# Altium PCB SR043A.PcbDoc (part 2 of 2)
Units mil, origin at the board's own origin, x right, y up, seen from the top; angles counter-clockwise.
Board outline 3937.01 x 3543.31 mil, 6 copper layers (Top Layer, Signal Layer 1, Signal Layer 2, Signal Layer 3, Signal Layer 4, Bottom Layer), stack 60.536 mil thick; 120 components, 36 nets, 230 pads, 513 vias.
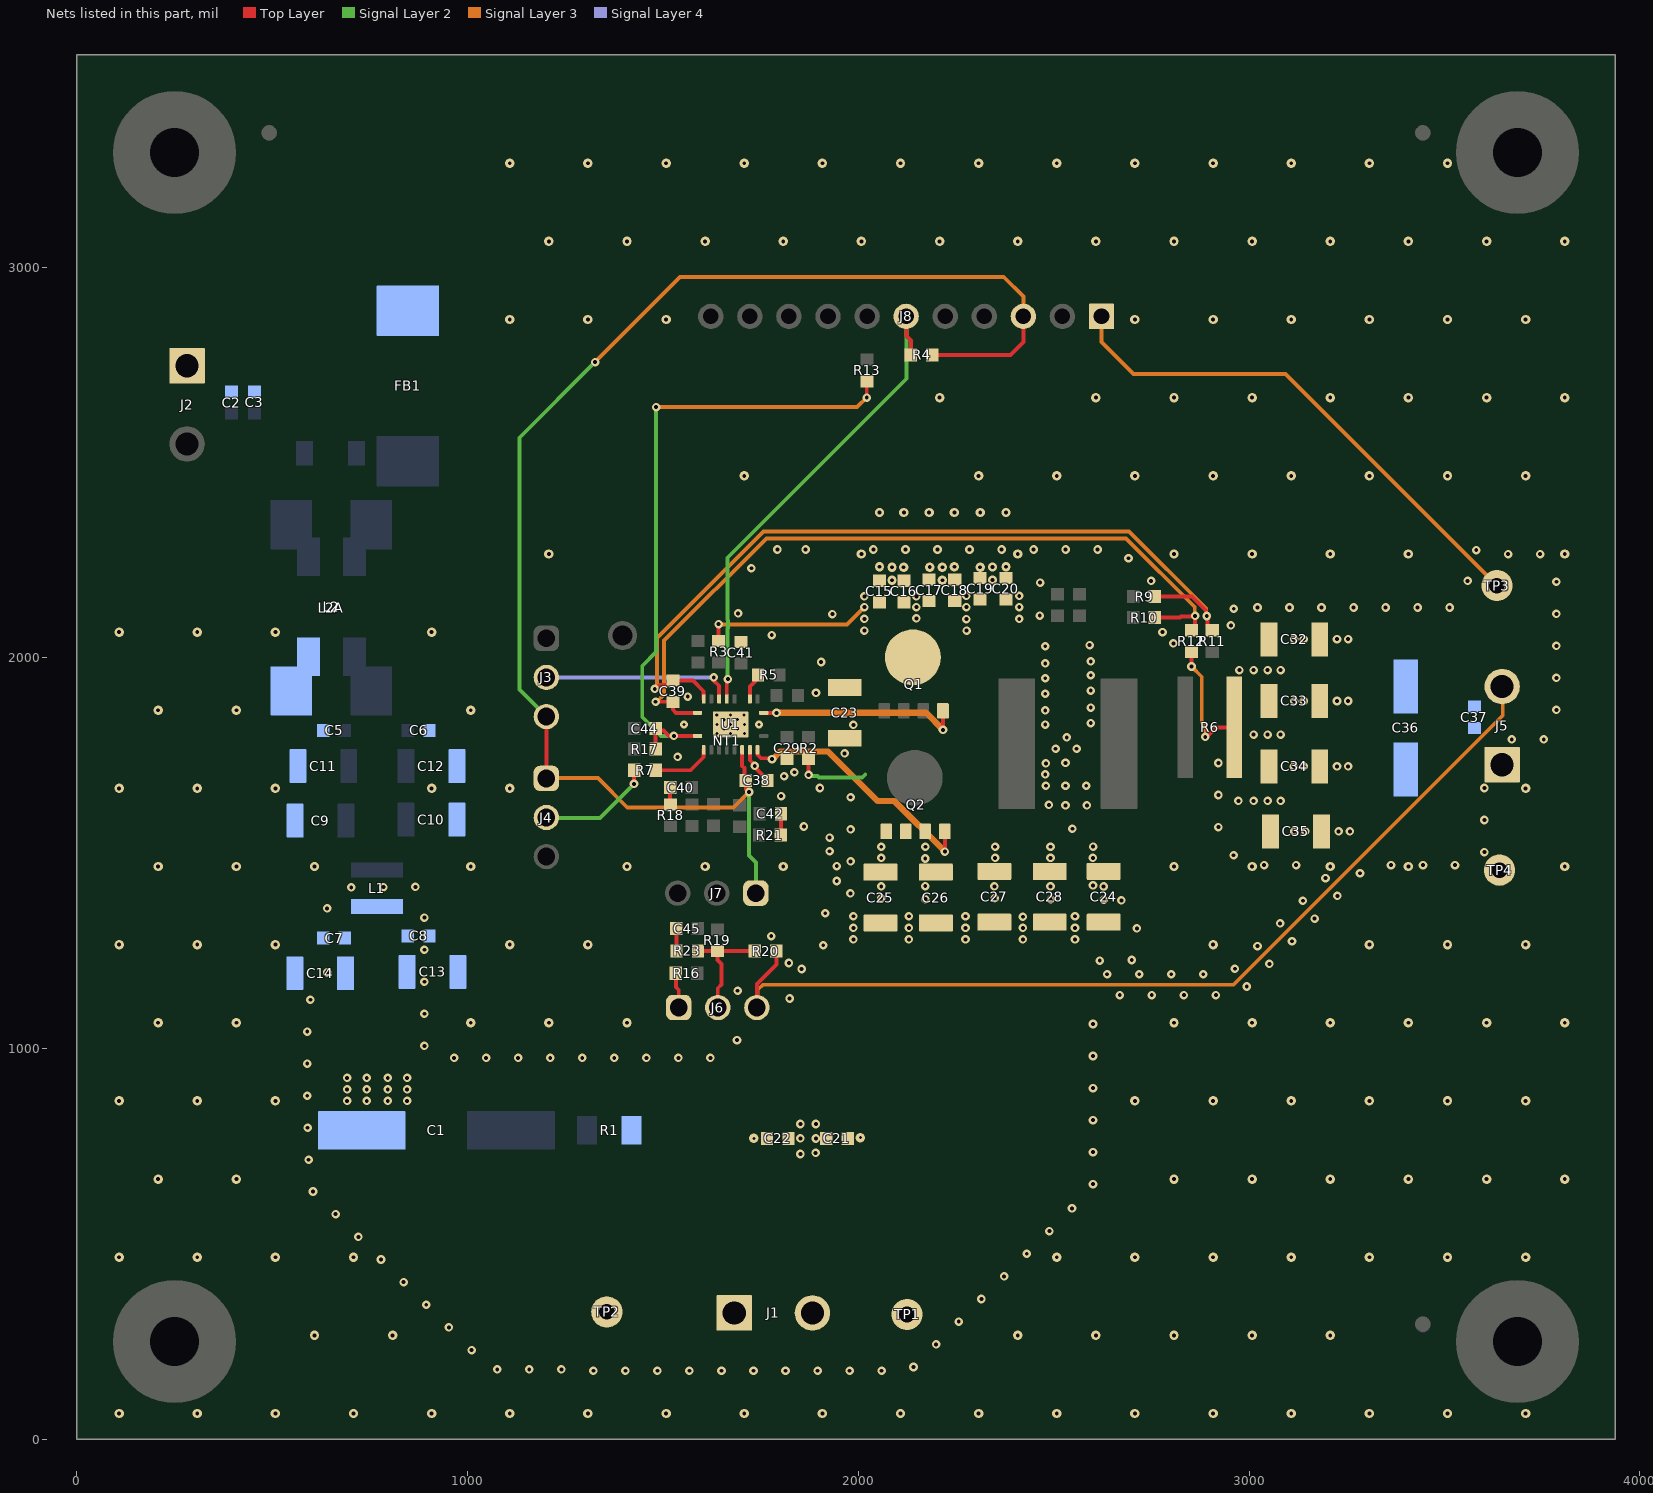
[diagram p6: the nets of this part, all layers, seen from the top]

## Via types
v1: diameter 22, hole 10, Top Layer to Bottom Layer, tented both sides, 318 vias
v2: diameter 24, hole 10, Top Layer to Bottom Layer, tented both sides, 178 vias
v3: diameter 19.68, hole 7.87, Top Layer to Bottom Layer, tented both sides, 15 vias
v4: diameter 24, hole 8, Top Layer to Bottom Layer, tented both sides, 2 vias

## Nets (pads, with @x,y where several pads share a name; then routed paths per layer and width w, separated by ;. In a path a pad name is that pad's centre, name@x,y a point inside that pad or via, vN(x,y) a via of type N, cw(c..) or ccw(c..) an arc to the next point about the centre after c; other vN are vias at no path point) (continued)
NetC39_1: C39.1 R10.1 R12.1 U1.19 | length 2005.3
  Top Layer w10: v1(1481.27,1887.68) 1524.54,1887.68 C39.1@1525.31,1886.91 1525.31,1867.22 1533.28,1859.25 U1.19@1588.58,1859.25 ; R10.1@2759.06,2103.12 2823,2103.12 2826.05,2106.16 2860.55,2106.16 v1(2861.88,2107.49) 2861.88,2079.63 R12.1@2852.78,2070.53
  Signal Layer 3 w10: v1(1481.27,1887.68) 1484.18,1887.68 1502.81,1906.31 1502.81,2043.95 1764.55,2305.69 2685.5,2305.69 2861.13,2130.07 2861.13,2108.25 v1(2861.88,2107.49)
NetC39_2: C39.2 R9.1 R11.2 U1.18 | length 2121.9
  Top Layer w10: v1(1478.94,1920.54) 1482.18,1920.54 1492.92,1931.28 1514.57,1931.28 C39.2@1525.31,1942.03 1525.54,1942.25 1576.61,1942.25 1604.25,1914.61 1604.25,1894.76 U1.18@1604.33,1894.69 ; R9.1@2759.06,2157.06 2854.02,2157.06 2889.46,2121.63 2889.46,2109.53 v1(2891.75,2107.23) 2894.05,2104.94 2894.05,2082.39 2894.18,2082.26 2894.18,2081.28 2904.93,2070.53 R11.2@2905.91,2070.53
  Signal Layer 3 w10: v1(1478.94,1920.54) 1478.94,1923.78 1484.44,1929.29 1484.44,2050.86 1757.15,2323.57 2692.9,2323.57 2889.46,2127.01 2889.46,2112.78 v1@2894,2108.24
NetC40_2: C40.2 R18.2 | length 43.6
  Top Layer w10: C40.2@1518.42,1667.92 1518.42,1626.15 R18.2@1519.73,1624.85
NetC42_2: C42.2 R21.1 | length 54.8
  Top Layer w10: R21.1@1801.15,1546.62 1802.02,1547.49 C42.2@1802.02,1601.08
NetC44_2: C44.2 R13.2 R17.2 U1.1 | length 1667.5
  Top Layer w10: R17.2@1481.4,1761.52 1481.4,1814.13 1501.2,1814.13 1515.13,1800.2 v1(1527.95,1800.2) U1.1@1588.58,1800.2 ; R17.2@1483.22,1769.18 R17.2@1484.2,1768.19 ; v1(2021.51,2666.01) 2021.51,2707.4 R13.2@2022.44,2708.33
  Signal Layer 2 w10: v1(1482.5,2641.59) 1482.5,2015.01 1447.03,1979.53 1447.03,1848.55 1495.38,1800.2 v1(1527.95,1800.2)
  Signal Layer 3 w10: v1(1482.5,2641.59) 1997.09,2641.59 v1(2021.51,2666.01)
NetC45_1: C45.1 R23.1 | length 57.6
  Top Layer w10: C45.1@1534.17,1307.09 1534.17,1250.46 R23.1@1534.84,1249.8
NetJ3_2: J3.2 U1.16 | length 489.4
  Top Layer w10: v1(1629.95,1949.89) 1629.86,1949.8 1629.86,1942.42 1643.7,1928.59 U1.16@1643.7,1894.69
  Signal Layer 4 w10: J3.2@1201.57,1949.89 v1(1629.95,1949.89)
NetJ4_2: J4.2 R7.2 | length 296
  Top Layer w10: v1(1425.97,1677.61) 1426.28,1677.92 1426.28,1682 R7.2@1426.28,1712.29
  Signal Layer 2 w10: J4.2@1201.57,1591.43 1202.88,1590.11 1338.47,1590.11 v1(1425.97,1677.61)
NetJ6_1: J6.1 R16.2 | length 90.8
  Top Layer w10: R16.2@1533.02,1192.73 1533.02,1157.11 1540.33,1149.81 J6.1@1540.33,1105.01
NetJ6_2: J6.2 R19.2 R20.1 R23.2 | length 298.1
  Top Layer w10: R23.2@1589.95,1249.8 1639.05,1249.8 R19.2@1639.31,1249.53 ; J6.2@1640.33,1105.01 1640.33,1154.32 1649.74,1163.72 1649.74,1216.73 1639.31,1227.16 R19.2@1639.31,1249.53 ; R20.1@1735.22,1249.53 R19.2@1639.31,1249.53
NetQ1_4: Q1.4 U1.11 | length 531.3
  Top Layer w10: U1.11@1757.87,1859.25 v1(1790.69,1859.25) ; v1(2216.73,1815.69) Q1.4@2216.73,1864.27
  Signal Layer 3 w10: v1@2210.83,1815.69 v1(2216.73,1815.69)
  Signal Layer 3 w16: v1(1790.69,1859.25) 2173.35,1859.25 v1@2216.73,1815.88
NetQ2_4: Q2.4 U1.9 | length 663.5
  Top Layer w10: U1.9@1742.13,1764.76 1742.13,1752.38 1751.32,1743.18 1776.89,1743.18 v1(1779.18,1740.89) ; v1(2221.48,1504.11) Q2.4@2221.48,1555.82
  Signal Layer 3 w10: v1(2221.48,1504.11) v1@2221.48,1505.82
  Signal Layer 3 w16: v1(1779.18,1740.89) 1780.81,1740.89 1800.43,1760.5 1922.18,1760.5 2049.28,1633.4 2092.66,1633.4 2220.24,1505.82 v1@2221.48,1505.82
NetR5_1: R5.1 U1.13 | length 62.2
  Top Layer w10: U1.13@1722.44,1894.69 1722.44,1926.6 1743.19,1947.35 R5.1@1743.19,1948.33
NetR7_1: R7.1 U1.2 | length 155.9
  Top Layer w10: R7.1@1481.4,1712.29 1570.95,1712.29 1604.25,1745.59 1604.25,1764.69 U1.2@1604.33,1764.76
PG: J8.6 R4.1 U1.15 | length 1275.7
  Top Layer w10: U1.15@1663.39,1894.69 1663.39,1942.59 v1(1666.31,1945.51) ; J8.6@2123.05,2874.02 2123.05,2824.02 2135.08,2811.99 R4.1@2135.08,2775.59
  Signal Layer 2 w10: v1(1666.31,1945.51) 1664.93,1946.89 1664.93,2075.13 1666.3,2076.5 1666.3,2096.27 1664.93,2097.64 1664.93,2256.31 2123.05,2714.43 2123.05,2873.41 J8.6@2122.44,2874.02
PGND: C5.2 C6.2 C7.2 C8.2 C9.1 C10.1 C11.1 C12.1 C13.1 C14.1 C15.2 C16.2 C17.2 C18.2 C19.2 C20.2 C21.2 C22.2 C23.1 C24.1 C25.1 C26.1 C27.1 C28.1 C29.1 C32.2 C33.2 C34.2 C35.2 C36.2 C37.2 C38.2 C41.2 J1.1 J5.1 L2.2 L2A.3 NT1.1 Q2.1 Q2.2 Q2.3 R1.2 TP2.1 TP4.1 U1.8 U1.20 | length 96.7
  Top Layer w10: U1.8@1722.44,1764.76 1722.44,1737.95 1735,1725.39 v1(1735,1723.62) 1737.3,1721.33 1737.3,1717.65 1767.34,1687.6 C38.2@1767.34,1686.62
  other v1: 1321.74,175.44 1403.74,175.44 1485.74,175.44 1567.74,175.44 1649.74,175.44 1731.74,175.44 1813.74,175.44 1895.74,175.44 1977.74,175.44 2059.74,175.44 1075.82,179.08 1157.82,179.08 1239.82,179.08 2141.18,185 1010.25,228.32 2199.16,242.98 952.27,286.3 2257.15,300.96 894.28,344.28 2315.13,358.94 836.3,402.26 2373.11,416.93 778.32,460.25 2431.1,474.91 720.33,518.23 2489.08,532.89 662.35,576.21 2547.06,590.88 604.37,634.19 2600.6,652.99 593.08,715.41 2600.67,734.99 590.49,797.37 2600.67,816.99 589.6,879.37 2600.67,898.99 589.6,961.37 965.46,976.14 1047.46,976.14 1129.46,976.14 1211.46,976.14 1293.46,976.14 1375.46,976.14 1457.46,976.14 1539.46,976.14 1621.46,976.14 2600.67,980.99 889.52,1007.07 1689.64,1021.69 589.6,1043.37 2600.67,1062.99 889.52,1089.07 597.5,1124.99 1824.18,1128.1 2669.16,1136.62 2751.16,1136.62 2833.16,1136.62 2915.16,1136.62 1691.12,1148.13 2994.09,1158.86 889.52,1171.07 2636.97,1190.27 2718.97,1190.27 2800.97,1190.27 2882.97,1190.27 640.45,1194.84 1855.03,1203.8 2963.74,1204.38 3052.07,1216.84 1822.22,1219.15 2617.9,1225.16 2699.88,1226.83 889.52,1253.07 3021.73,1262.37 1910.16,1264.5 3110.05,1274.83 1777.18,1287.67 2713.03,1307.77 3079.71,1320.35 3168.04,1332.81 889.52,1335.07 1915.36,1346.34 640.45,1358.84 3137.69,1378.33 2673.17,1379.43 2627.95,1381.43 2492.04,1381.72 2171.48,1382.57 2058.69,1384.59 2348.99,1384.55 3226.02,1390.79 1979.7,1397.18 702.25,1412.73 784.25,1413.39 866.25,1413.7 2058.69,1415.11 2348.15,1415.11 2491.85,1415.11 2627.77,1414.81 2171.24,1415.63 2600.67,1417.75 1944.79,1428.83 3195.68,1436.31 3284,1448.77 1944.79,1466.88 3038.73,1469.59 3120.73,1469.59 3363.32,1469.59 3445.32,1469.59 3527.32,1469.59 1980.19,1479.18 2171.24,1486.62 2058.69,1488.03 2350.12,1488.03 2491.85,1488.03 2600.39,1488.03 2960.74,1494.91 3602.23,1502.94 1926.57,1505.06 2058.69,1516.57 2171.48,1516.57 2350.12,1516.57 2491.85,1516.57 2600.88,1517.01 1926.57,1539.75 3115.7,1555.49 3144.14,1555.82 3229.52,1555.82 3258.07,1555.82 1980.19,1561.18 2548.06,1562.65 2921.5,1566.92 1860.81,1568.28 3602.23,1584.94 2530.32,1622.58 2584.94,1622.58 2487.86,1623.71 1980.19,1643.18 1802.42,1646.31 2921.5,1648.92 1901.7,1666.91 3602.23,1666.94 2479.95,1672.61 2530.32,1672.61 2583.35,1672.61 1810.02,1697.11 2478.51,1701.81 1836.49,1707.29 3114.99,1721.5 3139.76,1722.34 3225.15,1722.34 3253.69,1722.34 2479.95,1730.06 2530.32,1731.05 2921.5,1730.92 1537.72,1746.53 1965.17,1755.52 2504.95,1767.37 2558.75,1767.37 3672.42,1791.34 3754.42,1791.34 2533.57,1796.63 1987.2,1828.38 2478.51,1829.25 2594.9,1832.87 2478.51,1865.81 3786.55,1866.78 2594.9,1872.58 3115.35,1889.27 3139.76,1889.66 3225.15,1889.66 3253.69,1889.66 1563.46,1900.64 2478.51,1908.28 1891.64,1910.3 2594.9,1916.01 2478.51,1947.81 3786.55,1948.78 2594.9,1955.63 2478.51,1986.1 1904.98,1989.41 2594.9,1991.14 2478.51,2029.81 3786.55,2030.78 2591.91,2032.7 2806.22,2037.29 3115.35,2047.15 3139.76,2048.13 3225.15,2048.13 3253.69,2048.13 1778.49,2058.29 2778.59,2065.73 2953.53,2083.3 2464.31,2108.25 1933.66,2111.94 3786.55,2112.78 1692.54,2113.79 2960.95,2125.71 3021.61,2129.01 3103.61,2129.01 3185.61,2129.01 3267.61,2129.01 3349.61,2129.01 3431.61,2129.01 3513.61,2129.01 2465.3,2192.74 3786.55,2194.78 2749.6,2197.1 3559.4,2197.04 1726.2,2229.41 2691.62,2255.08 3663.06,2265.51 3745.06,2265.51 3581.71,2275.8 1792.71,2277.38 1865.36,2277.38 2038.71,2277.38 2120.71,2277.38 2202.71,2277.38 2284.71,2277.38 2366.71,2277.38 2448.71,2277.38 2530.71,2277.38 2612.71,2277.38
  other v2: 108,66 308,66 508,66 708,66 908,66 1108,66 1308,66 1508,66 1708,66 1908,66 2108,66 2308,66 2508,66 2708,66 2908,66 3108,66 3308,66 3508,66 3708,66 608,266 808,266 2408,266 2608,266 2808,266 3008,266 3208,266 108,466 308,466 508,466 708,466 2508,466 2708,466 2908,466 3108,466 3308,466 3508,466 3708,466 208,666 408,666 2808,666 3008,666 3208,666 3408,666 3608,666 3808,666 108,866 308,866 508,866 2708,866 2908,866 3108,866 3308,866 3508,866 3708,866 208,1066 408,1066 1008,1066 1208,1066 1408,1066 2808,1066 3008,1066 3208,1066 3408,1066 3608,1066 3808,1066 108,1266 308,1266 508,1266 1108,1266 1308,1266 2908,1266 3308,1266 3508,1266 3708,1266 208,1466 408,1466 608,1466 1008,1466 1408,1466 1608,1466 1808,1466 2808,1466 3008,1466 3208,1466 3408,1466 3808,1466 108,1666 308,1666 508,1666 908,1666 1108,1666 3708,1666 208,1866 408,1866 1008,1866 108,2066 308,2066 508,2066 908,2066 2086.25,2198.7 2215.33,2198.7 2343.38,2199.38 2086.25,2231.95 2116.04,2231.95 2182.86,2232.25 2215.33,2231.95 2311.77,2231.98 2054.23,2233.3 2245.99,2233.3 2343.38,2232.62 2377.95,2233.3 1208,2266 2008,2266 2408,2266 2808,2266 3008,2266 3208,2266 3408,2266 3808,2266 2054.23,2372.05 2116.73,2372.05 2181.1,2372.05 2245.99,2372.05 2312.01,2372.05 2377.95,2372.05 1708,2466 2308,2466 2508,2466 2708,2466 2908,2466 3108,2466 3308,2466 3508,2466 3708,2466 2208,2666 2608,2666 2808,2666 3008,2666 3208,2666 3408,2666 3608,2666 3808,2666 1108,2866 1308,2866 1508,2866 2708,2866 2908,2866 3108,2866 3308,2866 3508,2866 3708,2866 1208,3066 1408,3066 1608,3066 1808,3066 2008,3066 2208,3066 2408,3066 2608,3066 2808,3066 3008,3066 3208,3066 3408,3066 3608,3066 3808,3066 1108,3266 1308,3266 1508,3266 1708,3266 1908,3266 2108,3266 2308,3266 2508,3266 2708,3266 2908,3266 3108,3266 3308,3266 3508,3266
  other v3: 1673.23,1806.1 1638.04,1806.65 1708.2,1806.65 1655.76,1818 1690.69,1818 1553.86,1829.38 1745.67,1829.38 1637.8,1829.73 1673.23,1829.73 1708.66,1829.73 1655.76,1841.65 1690.69,1841.85 1637.73,1853.35 1673.23,1853.35 1707.92,1853.35
  other v4: 1732.58,770.18 2005.25,772.15
VCC: C38.1 J3.3 J4.1 J7.1 J8.3 R4.2 U1.7 | length 3699.5
  Top Layer w10: J4.1@1201.57,1691.43 J3.3@1201.57,1849.89 ; U1.7@1702.76,1764.76 1702.76,1723.39 1708.38,1717.77 1708.38,1690.46 C38.1@1712.23,1686.62 1712.23,1662.47 1718.08,1656.61 v1(1720.6,1656.61) ; R4.2@2188.86,2775.59 2390.05,2775.59 2422.44,2807.98 J8.3@2422.44,2874.02
  Signal Layer 2 w10: J3.3@1201.57,1849.89 1132.83,1918.62 1132.83,2563.47 v1(1326.25,2756.89) ; v1(1720.6,1656.61) 1720.6,1493.93 1738.4,1476.13 1738.4,1398.56 J7.1@1737.67,1397.83
  Signal Layer 3 w10: J4.1@1201.57,1680.71 1202.54,1680.71 1214.19,1692.36 1333.32,1692.36 1408.61,1617.07 1681.05,1617.07 v1(1720.6,1656.61) ; v1(1326.25,2756.89) 1543.96,2974.6 2372.27,2974.6 2422.44,2924.42 J8.3@2422.44,2874.02
VIN: C1.2 C7.1 C8.1 C13.2 C14.2 C15.1 C16.1 C17.1 C18.1 C19.1 C20.1 C21.1 C22.1 C23.2 C24.2 C25.2 C26.2 C27.2 C28.2 J1.2 L1.2 Q1.5-6 R2.2 R3.2 TP1.1 | length 627.4
  Top Layer w10: R3.2@1642.42,2043.35 R3.2@1642.51,2043.43 1642.42,2043.51 v1(1642.42,2086.39) ; v1(1872.94,1700.44) R2.2@1872.94,1741.62
  Signal Layer 2 w10: v1(1872.94,1700.44) 1875.23,1698.14 1895.11,1698.14 1899.52,1693.74 2010.06,1693.74 2017.87,1701.55
  Signal Layer 3 w10: v1(1642.42,2086.39) 1643.69,2085.12 1970.66,2085.12 v1(2015.48,2129.94)
  other v1: 1851.6,730.28 1890.74,733.19 1851.6,770.11 1891.35,769.95 1851.6,807.09 1891.35,807.09 691.72,866.14 741.97,866.14 795.72,866.14 845.21,866.14 691.72,895.67 741.97,895.67 795.72,895.67 845.22,895.67 691.72,925.2 741.97,925.2 795.72,925.2 845.22,925.2 1987.2,1279.53 2129.53,1279.53 2274.33,1279.53 2421.26,1279.53 2554.57,1279.53 1987.2,1309.06 2129.53,1309.06 2274.33,1309.06 2421.26,1309.06 2554.57,1309.06 2421.26,1337.45 1987.2,1338.58 2129.53,1338.58 2274.33,1338.58 2554.57,1338.58 2015.48,2069.63 2277.05,2069.79 2276.79,2099 2015.48,2099.89 2411.85,2099.89 2148.52,2101 2148.45,2129.94 2276.79,2129.94 2411.85,2129.94 2015.48,2157.33 2148.45,2157.33 2276.79,2158.79 2411.85,2158.79
VIN_EMI: C2.1 C3.1 FB1.1 J2.1
VOUT: C32.1 C33.1 C34.1 C35.1 C36.1 C37.1 J5.2 J6.3 J8.1 R6.2 R12.2 R20.2 TP3.1 | length 4156.4
  Top Layer w10: J6.3@1740.33,1105.01 1740.33,1165.01 1790.34,1215.01 R20.2@1790.34,1249.53 ; v1(2852.78,1978.03) R12.2@2852.78,2015.41 ; v1(2888.04,1797.89) 2891.21,1797.89 2915.27,1821.95 R6.2@2962.6,1821.95
  Signal Layer 2 w10: TP3.1@3634.54,2185.04 TP3.1@3647.27,2172.31 ; J5.2@3640.11,1902.9 J5.2@3640.79,1903.57 ; J5.2@3647.27,1927.24 J5.2@3647.99,1926.52
  Signal Layer 3 w10: J6.3@1740.33,1105.01 1742.7,1107.38 1742.7,1150.52 1755.63,1163.44 2960.74,1163.44 3649.38,1852.09 3649.38,1925.12 J5.2@3647.99,1926.52 ; J8.1@2622.44,2874.02 2622.44,2808.73 2704.79,2726.38 3093.2,2726.38 TP3.1@3634.54,2185.04 ; v1(2852.78,1978.03) 2879.05,1951.76 2879.05,1834.7 2888.04,1825.72 v1(2888.04,1797.89)
  other v1: 2972.84,1633.86 3011.96,1633.86 3047.46,1633.86 3080.71,1633.86 3011.96,1803.44 3047.46,1803.44 3080.71,1803.44 2975.51,1968.5 3011.96,1968.5 3047.46,1968.5 3080.71,1968.5
pads on no net: FID1.1 FID2.1 FID3.1 FID4.1 FID5.1 FID6.1 H1.1 H2.1 H3.1 H4.1 H5.0 H6.0 H7.0 H8.0

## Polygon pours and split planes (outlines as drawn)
NetC30_1 on Top Layer "TOP_LAYER_NETC30_1_P159" (solid, remove dead copper, pour order 159): 2038.6,1626.29 2038.6,1874.31 cw(c2049.24,1874.34) 2049.32,1884.98 2184.19,1883.93 cw(c2184.14,1876.63) 2191.43,1876.63 2191.43,1814.3 ccw(c2208.25,1814.3) 2208.25,1797.48 2331.67,1797.48 2354.29,1820.1 2354.29,1944.75 cw(c2358.38,1944.75) 2358.38,1948.84 2449.12,1948.84 cw(c2449.12,1942.15) 2455.8,1942.15 2455.8,1622.11 cw(c2442.96,1622.11) 2442.92,1609.27 2054.44,1610.4 cw(c2054.49,1626.29)
PGND on Top Layer "TOP_LAYER_PGND_P175" (solid, remove dead copper, pour order 175): 1572.33,1714.37 1501.08,1714.37 1501.08,1778.86 1572.33,1778.86
VIN on Top Layer "TOP_LAYER_VIN_P156" (solid, remove dead copper, pour order 156): 1985.24,1921.69 1919.19,1921.69 1919.19,1928.15 1919.19,1969.48 cw(c1929.25,1969.48) 1929.25,1979.53 1953.42,1979.53 ccw(c1953.42,1996.77) 1970.66,1996.77 1970.66,2170.16 2434.76,2170.16 2434.76,2077.78 2287.51,2077.78 2287.51,1921.69
VIN on Top Layer "TOP_LAYER_VIN_P154" (solid, remove dead copper, pour order 154): 2691.62,1358.02 2691.62,1246.57 1936.77,1246.57 1936.77,1358.02
PGND on Top Layer "TOP_LAYER_PGND_P160" (solid, remove dead copper, pour order 160): 2614.49,1393.11 1935.94,1393.11 1935.94,1580.22 2614.74,1580.22
PGND on Top Layer "TOP_LAYER_PGND_P155" (solid, remove dead copper, pour order 155): 2434.69,2244.14 1972.15,2244.14 1970.51,2245.78 1970.51,2431.25 2434.94,2431.25
NetC31_2 on Top Layer "TOP_LAYER_NETC31_2_P158" (solid, remove dead copper, pour order 158): 2614.49,1609.07 2856.69,1609.07 2856.69,2008.06 2848.88,2015.87 2614.74,2015.87
VOUT on Top Layer "TOP_LAYER_VOUT_P157" (solid, remove dead copper, pour order 157): 3093.45,1491 3093.45,2102.26 3002.77,2102.26 2942.91,2042.4 2942.91,1543.02 2994.94,1491
PGND on Top Layer "TOP_LAYER_PGND_P161" (solid, remove dead copper, pour order 161): -0.58,0.56 -0.58,3543.87 3936.42,3543.87 3936.42,0.56
AGND on Top Layer "TOP_LAYER_AGND_P153" (solid, remove dead copper, pour order 153): 1779.96,1589.07 1779.96,1532.25 1771.38,1523.67 1394.04,1523.67 1361.41,1556.3 1361.41,1859.48 1377.57,1875.64 1447.03,1875.64 1447.03,1835.62 1488.29,1835.62 1488.29,1607.1 1500.07,1595.32 1773.71,1595.32
VIN on Top Layer "TOP_LAYER_VIN_P152" (solid, remove dead copper, pour order 152): 1940.03,712.31 1939.56,712.78 1799.86,712.78 1799.86,827.59 1940.03,827.59
VIN on Signal Layer 2 "SIGNAL_LAYER_2_VIN_P164" (solid, remove dead copper, pour order 164): 2579.26,1501.16 2579.26,653.36 2122.76,196.85 1283.17,196.85 1279.53,200.49 1068.35,200.49 616.63,652.22 616.63,954.72 1581.94,954.72 1657.75,954.72 1936.56,1261.72 1936.56,1323.76 1972.38,1359.58 2001.6,1388.8 2001.6,2172.96 2457.1,2172.96 2457.1,1623.32
VOUT on Signal Layer 2 "SIGNAL_LAYER_2_VOUT_P163" (solid, remove dead copper, pour order 163): 3008.11,2107.6 3580.81,2107.6 3580.81,2244.09 3765.14,2244.09 3765.14,2107.6 3765.14,1812.75 3580.81,1812.75 3580.81,1491 2994.94,1491 2942.91,1543.02 2942.91,2042.4
PGND on Signal Layer 2 "SIGNAL_LAYER_2_PGND_P165" (solid, remove dead copper, pour order 165): 0,0 0,3543.31 3937.01,3543.31 3937.01,0
NetC5_1 on Bottom Layer "BOTTOM_LAYER_NETC5_1_P169" (solid, remove dead copper, pour order 169): 666.78,2073.08 666.78,1431.68 869.09,1431.68 869.09,2074.62 852.9,2090.76 683.95,2090.3
PGND on Bottom Layer "BOTTOM_LAYER_PGND_P174" (solid, remove dead copper, pour order 174): -0.49,-5.7 6.78,2090.81 1013.29,2090.81 1013.29,3537.6 3936.52,3537.6 3936.52,-5.7
NetC4_1 on Bottom Layer "BOTTOM_LAYER_NETC4_1_P170" (solid, remove dead copper, pour order 170): 675.88,2578.63 675.88,2165.44 695.66,2145.67 935.04,2145.67 953.03,2163.66 953.03,2580.92 927.72,2606.23 703.48,2606.23
"EMI GND" on Bottom Layer "BOTTOM_LAYER_EMI_GND_P173" (solid, remove dead copper, pour order 173): 25.49,3543.31 616.14,3543.31 935.04,3543.31 935.04,3281.98 935.04,3113.11 625.44,3113.11 625.44,2160.92 600.35,2135.83 25.49,2135.83
VIN_EMI on Bottom Layer "BOTTOM_LAYER_VIN_EMI_P172" (solid, remove dead copper, pour order 172): 196.12,3090.55 886.34,3090.55 942.97,3033.93 942.97,2742.04 871.88,2670.96 173.9,2670.96 127.08,2717.77 127.08,3021.51
VOUT on Bottom Layer "BOTTOM_LAYER_VOUT_P168" (solid, remove dead copper, pour order 168): 3703.36,1855.61 3366.14,1855.61 3366.14,1998.44 3702.89,1998.44
VIN on Bottom Layer "BOTTOM_LAYER_VIN_P171" (solid, remove dead copper, pour order 171): 661.86,1391 661.86,1108.76 611.01,1108.76 611.01,726.38 868.11,726.38 868.11,1392.66
PGND on Signal Layer 1 "SIGNAL_LAYER_1_PGND_P162" (solid, remove dead copper, pour order 162): 984.25,0 0,0 0,1965.83 0,3543.31 3937.01,3543.31 3937.01,0
PGND on Signal Layer 3 "SIGNAL_LAYER_3_PGND_P166" (solid, remove dead copper, pour order 166): 0,0 0,3543.31 3937.01,3543.31 3937.01,0
PGND on Signal Layer 4 "SIGNAL_LAYER_4_PGND_P167" (solid, remove dead copper, pour order 167): 0,0 0,3543.31 3937.01,3543.31 3937.01,0

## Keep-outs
Keep-Out Layer:
  lines w10: 6.82,0 3937.01,0 3937.01,3543.31 6.82,3543.31 6.82,0
  text ".Layer_Name" at 577,-858.49 h60

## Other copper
Top Layer:
  pour cut-out: 1712,1876.21 1697.24,1876.21 1697.24,1902.78 1711.8,1917.34
  pour cut-out: 1899.67,1816.42 1899.67,1843.96 1854.24,1843.96 1854.24,1816.42
  text ".Layer_Name" at 577,-858.49 h60
Signal Layer 1:
  text ".Layer_Name" at 570.87,-856.3 h60
Signal Layer 2:
  text ".Layer_Name" at 570.87,-856.3 h60
Signal Layer 3:
  text ".Layer_Name" at 570.87,-856.3 h60
Signal Layer 4:
  text ".Layer_Name" at 570.87,-856.3 h60
Bottom Layer:
  text ".Layer_Name" at 577,-858.49 h60

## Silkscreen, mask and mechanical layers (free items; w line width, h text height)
Top Overlay:
  drawing of 153 lines, arcs and shapes, not listed
  text "LM5190QEVM-400" at 640.37,3145.1 h108.27
  text "'.PRJ_Number'.PCB_Rev" at 651.64,3021.65 h108.27
  text "FB" at 2342.52,2974.6 h30 r90
  text "EN" at 1642.52,2968.6 h30 r90
  text "AGND" at 1744,2968.6 h30 r90
  text "ILIM/IMON" at 1842.52,2968.6 h30 r90
  text "AGND" at 1950.43,2968.6 h30 r90
  text "ISET" at 2043.64,2968.6 h30 r90
  text "PG" at 2148.41,2968.6 h30 r90
  text "COMP" at 2239.76,2968.6 h30 r90
  text "VCC" at 2442.52,2968.6 h30 r90
  text "BIAS" at 2535.24,2968.6 h30 r90
  text "VOUT" at 2636.44,2968.6 h30 r90
  text "VIN_EMI+" at 94.58,2916.21 h40
  text "4A MAX" at 594.35,2546.36 h40 r90
  text "VIN_EMI-" at 95.34,2310.66 h40
  text "MODE: J3" at 410.97,2065.48 h30
  text "VOUT+" at 3561.22,2060.23 h40
  text "AGND" at 1019.29,2040.72 h30
  text "1-2: PFM" at 415.07,1978.97 h30
  text "FPWM/SYNC" at 874.11,1939.12 h30
  text "2-3: FPWM" at 409.07,1916.7 h30
  text "OPEN: EXT SYNC" at 409.07,1859.62 h30
  text "VCC" at 1047.42,1831.94 h30
  text "RT: J4" at 399.16,1708.98 h30
  text "8A MAX" at 3379.83,1706.5 h40 r90
  text "VCC" at 1039,1677.71 h30
  text "1-2: DRSS ON" at 403.25,1622.47 h30
  text "RT" at 1059.15,1576.17 h30
  text "2-3: DRSS OFF" at 397.25,1560.2 h30
  text "VOUT-" at 3559.26,1544.01 h40
  text "AGND" at 1019.29,1468.44 h30
  text "FB: J7" at 907.82,1370.98 h30
  text "VCC" at 1793.67,1370.36 h30
  text "AGND" at 1349.11,1366.07 h30
  text "FB" at 1734,1298.42 h30
  text "1-2: 12VOUT" at 907.82,1287.98 h30
  text "2-3: 5VOUT" at 904.62,1228.41 h30
  text "OPEN: ADJ VOUT" at 910.62,1160.64 h30
  text "TRIM" at 1551.78,900.72 h30 r90
  text "BODE-" at 1659.21,900.72 h30 r90
  text "BODE+" at 1759.04,900.72 h30 r90
  text "7A MAX" at 1665.98,586.71 h40
  text "VIN-" at 1312.8,173.26 h40
  text "VIN+" at 2061.59,173.32 h40
  text ".Layer_Name" at 577,-858.49 h60
Bottom Overlay:
  text ".Layer_Name" at 577,-858.49 h60
Top Paste:
  text ".Layer_Name" at 577,-858.49 h60
Bottom Paste:
  text ".Layer_Name" at 577,-858.49 h60
Top Solder:
  text ".Layer_Name" at 577,-858.49 h60
  text ".Layer_Name" at 577,-858.49 h60
Bottom Solder:
  text ".Layer_Name" at 577,-858.49 h60
Drill Guide:
  text ".Layer_Name" at 577,-858.49 h60
M1 Board Outline:
  lines w10: 6.65,0 3937.01,0 3937.01,3543.31 6.65,3543.31 6.65,0
  text ".Layer_Name" at 577,-858.49 h60
M2 Board Dimensions:
  rectangle: 0,-275 125,-150
  rectangle: 125,-400 500,-275
  lines w7: 0,-275 1000,-275 ; 125,-400 125,-150 ; 250,-400 250,-150 ; 500,-400 500,-150 ; 750,-400 750,-150 ; 0,-400 1000,-400 1000,-150 0,-150 0,-400
  text ".Layer_Name" at 577,-858.49 h60
M3 3D STEP Top:
  text ".Layer_Name" at 577,-858.49 h60
M4 3D STEP Bottom:
  text ".Layer_Name" at 577,-858.49 h60
M5 Assembly Top:
  lines w10: -292,-930.17 6308,-930.17 ; -292,-726.83 6310,-726.83 ; -292,-523.5 -292,-1133.5 3713,-1133.5 6310,-1133.5 6310,-523.5 -291.5,-523.5 -291.5,-1133.5 1284,-1133.5 ; 2173,-1133.5 2173,-523.5 ; 3440,-726.83 3440,-523.5 ; 4280,-726.83 4280,-523.5 ; 4902,-1140 4902,-937.17
  text "COMPONENTS MARKED 'DNP' SHOULD NOT BE POPULATED." at 1153.5,-318.5 h60
  text "ASSEMBLY VARIANT:" at 1153,-434 h60
  text ".VariantName" at 2189,-434 h60
  text "PCB VIEWED FROM TOP SIDE" at -228.5,-655.67 h60
  text "BOARD #:" at 2248,-655.67 h60
  text ".PRJ_Number" at 2793.5,-655.67 h60
  text "REV:" at 3638,-655.67 h60
  text ".PCB_Rev" at 3929.5,-655.67 h60
  text "SVN REV:" at 4476,-655.67 h60
  text ".VersionControl_RevNumber" at 4982,-655.67 h60
  text "TID #:" at 2248,-859 h60
  text ".TID" at 2793.5,-859 h60
  text "PLOT NAME =" at -228.5,-1064.34 h60
  text ".plot_File_Name" at 577,-1064.34 h60
  text "GENERATED    :" at 2250,-1064.34 h60
  text ".Print_Date" at 3119.5,-1064.34 h60
  text ".Print_Time" at 3848.5,-1064.34 h60
  text "TEXAS INSTRUMENTS" at 5113,-1064.34 h60
M6 Assembly Bottom:
  lines w10: -292.5,-727.33 6309.5,-727.33 ; -290.5,-930.67 6309.5,-930.67 ; 1115.5,-1140.5 1115.5,-937.67 ; 1737.5,-727.33 1737.5,-524 ; 2577.5,-727.33 2577.5,-524 ; 3844.5,-1134 3844.5,-524 ; 4733.5,-1134 6309,-1134 6309,-524 -292.5,-524 -292.5,-1134 2304.5,-1134 6309.5,-1134 6309.5,-524
  text "COMPONENTS MARKED 'DNP' SHOULD NOT BE POPULATED." at 6102,-318 h60
  text ".VariantName" at 5058,-434 h60
  text "ASSEMBLY VARIANT:" at 6097,-434 h60
  text ".VersionControl_RevNumber" at 1035.5,-656.17 h60
  text "SVN REV:" at 1541.5,-656.17 h60
  text ".PCB_Rev" at 2088,-656.17 h60
  text "REV:" at 2379.5,-656.17 h60
  text ".PRJ_Number" at 3224,-656.17 h60
  text "BOARD #:" at 3769.5,-656.17 h60
  text "PCB VIEWED FROM BOTTOM SIDE" at 6246,-656.17 h60
  text ".TID" at 3224,-859.5 h60
  text "TID #:" at 3769.5,-859.5 h60
  text "TEXAS INSTRUMENTS" at 904.5,-1064.84 h60
  text ".Print_Time" at 2169,-1064.84 h60
  text ".Print_Date" at 2898,-1064.84 h60
  text "GENERATED    :" at 3767.5,-1064.84 h60
  text ".plot_File_Name" at 5440.5,-1064.84 h60
  text "PLOT NAME =" at 6246,-1064.84 h60
M9 Title Sheet:
  drawing of 57 lines, arcs and shapes, not listed
  text "1" at 739.84,8036.5 h70
  text "2" at 3235.5,8036.5 h70
  text "3" at 5724.84,8036.5 h70
  text "4" at 8231.51,8036.5 h70
  text "5" at 10730.5,8036.5 h70
  text "6" at 13235.5,8036.5 h70
  text "A" at -416.5,6893.5 h70
  text "A" at 14383.5,6893.5 h70
  text "B" at -416.5,4513.5 h70
  text "B" at 14383.5,4513.5 h70
  text "C" at -416.5,2138.5 h70
  text "C" at 14383.5,2138.5 h70
  text "PROJECT TITLE:" at 11343.5,277.5 h45
  text ".PRJ_Title" at 11393.5,144.17 h70
  text "DESIGNED FOR:" at 11343.5,-23.5 h45
  text ".PRJ_Customer" at 11393.5,-163.5 h70
  text "D" at -416.5,-231.5 h70
  text "D" at 14383.5,-231.5 h70
  text "FILE NAME:" at 11343.5,-323.5 h45
  text ".PCB_File_Name_No_Path" at 11393.5,-443.5 h70
  text "Texas Instruments (TI) and/or its licensors do not warrant the accuracy or completeness of this specification" at 6374,-605.34 h45
  text "ENGINEER:" at 11343.5,-613.5 h45
  text "LAYOUT BY:" at 12848.5,-613.5 h45
  text "or any information contained therein. TI and/or its licensors do not warrant that this design will meet" at 6329.01,-718 h45
  text ".PRJ_Engineer" at 11393.5,-768.49 h70
  text ".PCB_Layout" at 12899,-768.49 h70
  text "the specifications, will be suitable for your application or fit for any particular purpose, or will operate in" at 6329.01,-830.67 h45
  text ".Layer_Name" at 577,-858.49 h60
  text "ALTIUM DESIGNER VERSION:" at 12848.5,-923.5 h45
  text "an implementation. TI and/or its licensors do not warrant that the design is production worthy. You should" at 6329.01,-943.33 h45
  text "completely validate and test your design implementation to confirm the system functionality for your application." at 6374,-1056 h45
  text ".print_Scale" at 11393.5,-1056.83 h70
  text ".Application_BuildNumber" at 12899,-1056.83 h70
  text "1" at 739.84,-1263.5 h70
  text "2" at 3235.5,-1263.5 h70
  text "3" at 5724.84,-1263.5 h70
  text "4" at 8231.51,-1263.5 h70
  text "5" at 10730.5,-1263.5 h70
  text "6" at 13235.5,-1263.5 h70
M10 Fab Notes:
  drawing of 189 lines, arcs and shapes, not listed
  text "DESIGN INFORMATION" at 12382.02,6356.17 h60
  text "MIN. TRACK WIDTH:" at 11737.46,6224.05 h60
  text "8" at 12833.7,6224.05 h60
  text "MIL" at 12988.46,6224.05 h60
  text "7.874" at 12667.32,6102.36 h60
  text "MIN. CLEARANCE:" at 11737.46,6099.92 h60
  text "MIL" at 12988.46,6099.92 h60
  text "MIN. VIA PAD SIZE:" at 11737.46,5975.8 h60
  text "24" at 12803.71,5975.8 h60
  text "MIL" at 12988.46,5975.8 h60
  text "0.05mm (2MIL)" at 12432.46,5845.9 h60
  text "MINIMUM ANNULAR RING" at 11408.23,5837.67 h60
  text "EXTERNAL" at 13140.46,5837.67 h60
  text "PER" at 11608.23,5727.55 h60
  text "IPC-D-275 CLASS 2 LEVEL C" at 11828.23,5727.54 h60
  text "MIL, HOLES" at 13316.46,5627.07 h60
  text "+/-" at 12924,5618.48 h60
  text "+/-" at 13778,5618.48 h60
  text "REGISTRATION TOLERANCES:" at 11408.23,5617.42 h60
  text "METAL" at 12608,5617.42 h60
  text "5" at 13184.2,5617.42 h60
  text "3" at 14017.2,5617.42 h60
  text "MIL" at 14133.46,5617.42 h60
  text "HOLE SIZE TOLERANCE (UNLESS OTHERWISE SPECIFIED):" at 11408.23,5519.1 h60
  text "+/-" at 13778,5516.23 h60
  text "3" at 14017.2,5515.17 h60
  text "MIL" at 14133.46,5515.17 h60
  text "MATERIAL:" at 11333.46,5377.52 h60
  text "FR-4 High Tg" at 12319.9,5249 h60
  text "X" at 12175.46,5241.01 h60
  text "FR-4" at 11754.46,5236.49 h60
  text "OTHER" at 13242.46,5236.49 h60
  text "62 MIL (1.6mm) +/-10%" at 12074.56,5093.46 h60
  text "X" at 11954.46,5091.01 h60
  text "THICKNESS:" at 11408.23,5085.24 h60
  text "OTHER" at 13359.46,5085.24 h60
  text "TOLERANCE:" at 11408.23,4946.92 h60
  text "X" at 12256.46,4946.92 h60
  text "ANSI IPC-6012 TYPE 3 CLASS 2" at 12434.48,4946.92 h60
  text "OTHER +/-" at 12434.46,4802.73 h60
  text "BOW & TWIST:" at 11408.23,4657.54 h60
  text "X" at 12256.46,4657.54 h60
  text "ANSI IPC-6012 TYPE 3 CLASS 2" at 12434.48,4657.54 h60
  text "OTHER +/-" at 12434.46,4510.85 h60
  text "DRILLING:" at 11333.46,4380.23 h60
  text "NC_DRILL FILES" at 13094.46,4275.04 h60
  text "REFERENCE:" at 11408.23,4271.1 h60
  text "X" at 12065.46,4271.01 h60
  text "AS SHOWN" at 12243.46,4271.1 h60
  text "X" at 12966.46,4271.1 h60
  text "OTHER" at 13392.46,4128.85 h60
  text "PTH COPPER THICKNESS:" at 11407.91,4125.32 h60
  text "X" at 12547.14,4125.32 h60
  text "20-30 um" at 12675.14,4125.32 h60
  text "BOARD FINISH:" at 11333.46,3977.73 h60
  text "SILKSCREEN:" at 11488.68,3867.6 h60
  text "X" at 12446.46,3867.6 h60
  text "TOP" at 12563.46,3867.6 h60
  text "X" at 12956.46,3867.6 h60
  text "BOTTOM" at 13074.46,3867.6 h60
  text "SILKSCREEN COLOR:" at 11488.68,3712.41 h60
  text "X" at 12445.46,3712.41 h60
  text "WHITE" at 12563.46,3712.41 h60
  text "OTHER" at 13074.46,3712.41 h60
  text "X" at 12576.46,3568.96 h60
  text "GREEN" at 12694.46,3568.96 h60
  text "OTHER" at 13312.46,3568.96 h60
  text "SOLDER RESIST COLOR:" at 11488.68,3562.1 h60
  text "X" at 12576.46,3414.71 h60
  text "MATTE" at 12694.46,3414.71 h60
  text "SEMI-GLOSS" at 13312,3414.07 h60
  text "IMMERSION GOLD (ENIG)" at 12394.46,3241.94 h60
  text "ENEPIG" at 13732,3234.72 h60
  text "SURFACE FINISH:" at 11333.46,3233.72 h60
  text "X" at 12216.46,3233.72 h60
  text "IMM. TIN/SILVER OR EQUIV" at 11663,3096.4 h60
  text "OTHER" at 13094.46,3092.47 h60
  text "ARRAY/PANEL:" at 11333.46,2937.09 h60
  text "CUT AND TRIM PER M1 BOARD OUTLINE" at 12394.46,2928.87 h60
  text "N.C. ROUTE" at 12394.46,2792.9 h60
  text "X" at 13082.46,2792.9 h60
  text "V. SCORE" at 13260.46,2792.9 h60
  text "CERTIFICATION:" at 11333.46,2663.77 h60
  text "MATERIALS AND WORKMANSHIP FOR ALL PCBS" at 12058.46,2663.77 h60
  text "TO MEET OR EXCEED THE REQUIREMENTS OF:" at 12058.46,2569.71 h60
  text "X" at 11695.97,2441.08 h60
  text "ANSI IPC-A-600F CLASS ->" at 11823.96,2441.08 h60
  text "X" at 13471.97,2441.08 h60
  text "2" at 13581.96,2441.08 h60
  text "1" at 13266.96,2439.58 h60
  text "3" at 13935.96,2439.58 h60
  text "X" at 12507.97,2293.39 h60
  text "RoHS" at 12635.96,2293.39 h60
  text "OTHER" at 13280.36,2293.39 h60
  text "PER ORDER" at 13677.42,2293.39 h60
  text "ALL BOARDS MUST MEET OR EXCEED UL94-V0 REQUIREMENTS." at 11361,2139.57 h60
  text "PCB MUST BEAR THE UL94V-0 UL REGISTERED MATERIAL ID NUMBER" at 11361,2023.5 h60
  text "ADDITIONAL REQUIREMENTS:" at 11333.46,1854.08 h60
  text "MICROSECTION:" at 11408.23,1746.95 h60
  text "YES" at 12313.96,1746.95 h60
  text "REQUIRED" at 13175.46,1602.62 h60
  text "BARE BOARD ELEC. TEST:" at 11408.23,1599.76 h60
  text "NONE" at 12713.96,1599.76 h60
  text "X" at 13057.46,1599.76 h60
  text "PER ORDER" at 13767.46,1599.76 h60
  text "X" at 11466.54,1456.69 h60
  text "7.874 MIL VIAS REQUIRE NON-CONDUCTIVE FILL AND PLANARIZE" at 11576.38,1394.82 h59 r359.85
  text "XX MIL VIAS REQUIRE CONDUCTIVE FILL AND PLANARIZE" at 11584.38,1290.84 h60
  text "OUTER XX MIL TRACES REQUIRE 50 OHM SINGLE-ENDED IMPEDANCE" at 11583.39,1127.46 h58
  text "LAYER 2 & 3 (INNER LAYERS) XX MIL WIDE, XX MIL SPACE / TRACES REQUIRE 100 OHM DIFFERENTIAL IMPEDANCE" at 11575.39,891.74 h60
  text ".Layer_Name" at 577,-858.49 h60
M11 Gerber Information:
  lines w10: -292,-930.17 6308,-930.17 ; -292,-726.83 6310,-726.83 ; -292,-523.5 -292,-1133.5 3713,-1133.5 6310,-1133.5 6310,-523.5 -291.5,-523.5 -291.5,-1133.5 1284,-1133.5 ; 2173,-1133.5 2173,-523.5 ; 3440,-726.83 3440,-523.5 ; 4280,-726.83 4280,-523.5 ; 4902,-1140 4902,-937.17
  text "ALL ARTWORK VIEWED FROM TOP SIDE" at -228.5,-655.67 h60
  text "BOARD #:" at 2248,-655.67 h60
  text ".PRJ_Number" at 2793.5,-655.67 h60
  text "REV:" at 3638,-655.67 h60
  text ".PCB_Rev" at 3929.5,-655.67 h60
  text "SVN REV:" at 4476,-655.67 h60
  text ".VersionControl_RevNumber" at 4982,-655.67 h60
  text "LAYER NAME =" at -228.5,-858.49 h60
  text "TID #:" at 2248,-859 h60
  text ".TID" at 2793.5,-859 h60
  text "PLOT NAME =" at -228.5,-1064.34 h60
  text ".plot_File_Name" at 577,-1064.34 h60
  text "GENERATED    :" at 2250,-1064.34 h60
  text ".Print_Date" at 3119.5,-1064.34 h60
  text ".Print_Time" at 3848.5,-1064.34 h60
  text "TEXAS INSTRUMENTS" at 5113,-1064.34 h60
M12 Stackup:
  drawing of 399 lines, arcs and shapes, not listed
  text "Layer" at 9821.59,7874.94 h60
  text "Name" at 10231.51,7874.94 h60
  text "Material" at 11171.25,7874.94 h60
  text "Thickness" at 12031.02,7874.94 h60
  text "Constant" at 12680.85,7874.94 h60
  text "Board Layer Stack" at 13250.71,7874.94 h60
  text "Top Overlay" at 10231.51,7754.94 h60
  text "Top Solder" at 10231.51,7634.94 h60
  text "Solder Resist" at 11171.25,7634.94 h60
  text "0.40mil" at 12031.02,7634.94 h60
  text "3.5" at 12680.85,7634.94 h60
  text "1" at 9821.59,7514.94 h60
  text "Top Layer" at 10231.51,7514.94 h60
  text "CF-005" at 11171.25,7514.94 h60
  text "2.76mil" at 12031.02,7514.94 h60
  text "Dielectric 1" at 10231.51,7394.94 h60
  text "FR-4 High Tg" at 11171.25,7394.94 h60
  text "6.00mil" at 12031.02,7394.94 h60
  text "4.1" at 12680.85,7394.94 h60
  text "2" at 9821.59,7274.94 h60
  text "Signal Layer 1" at 10231.51,7274.94 h60
  text "CF-005" at 11171.25,7274.94 h60
  text "2.76mil" at 12031.02,7274.94 h60
  text "Dielectric 2" at 10231.51,7154.94 h60
  text "FR-4 High Tg" at 11171.25,7154.94 h60
  text "10.00mil" at 12031.02,7154.94 h60
  text "4.1" at 12680.85,7154.94 h60
  text "3" at 9821.59,7034.94 h60
  text "Signal Layer 2" at 10231.51,7034.94 h60
  text "CF-005" at 11171.25,7034.94 h60
  text "2.76mil" at 12031.02,7034.94 h60
  text "Dielectric 3" at 10231.51,6914.94 h60
  text "FR-4 High Tg" at 11171.25,6914.94 h60
  text "12.00mil" at 12031.02,6914.94 h60
  text "4.8" at 12680.85,6914.94 h60
  text "4" at 9821.59,6794.94 h60
  text "Signal Layer 3" at 10231.51,6794.94 h60
  text "CF-005" at 11171.25,6794.94 h60
  text "2.76mil" at 12031.02,6794.94 h60
  text "Dielectric 4" at 10231.51,6674.94 h60
  text "FR-4 High Tg" at 11171.25,6674.94 h60
  text "10.00mil" at 12031.02,6674.94 h60
  text "4.1" at 12680.85,6674.94 h60
  text "5" at 9821.59,6554.94 h60
  text "Signal Layer 4" at 10231.51,6554.94 h60
  text "CF-005" at 11171.25,6554.94 h60
  text "2.76mil" at 12031.02,6554.94 h60
  text "Dielectric 5" at 10231.51,6434.94 h60
  text "FR-4 High Tg" at 11171.25,6434.94 h60
  text "6.00mil" at 12031.02,6434.94 h60
  text "4.1" at 12680.85,6434.94 h60
  text "6" at 9821.59,6314.94 h60
  text "Bottom Layer" at 10231.51,6314.94 h60
  text "CF-005" at 11171.25,6314.94 h60
  text "2.76mil" at 12031.02,6314.94 h60
  text "Bottom Solder" at 10231.51,6194.94 h60
  text "Solder Resist" at 11171.25,6194.94 h60
  text "0.40mil" at 12031.02,6194.94 h60
  text "3.5" at 12680.85,6194.94 h60
  text "Bottom Overlay" at 10231.51,6074.94 h60
  text "Total board thickness:" at 9821.59,5954.94 h60
  text "61.34mil" at 12031.02,5954.94 h60
  text ".Layer_Name" at 577,-858.49 h60
M13 Component Bodies Top:
  text ".Layer_Name" at 577,-858.49 h60
M14 Component Bodies Bottom:
  text ".Layer_Name" at 577,-858.49 h60
M15 Courtyards Top:
  text ".Layer_Name" at 577,-858.49 h60
M16 Courtyards Bottom:
  text ".Layer_Name" at 577,-858.49 h60
Drill Drawing:
  circle w10: c5363.63,2793.79 r16.56
  circle w10: c5363.63,2793.79 r27.59
  circle w10: c5363.63,2421.26 r27.59
  lines w10: 5336.04,2573.03 5391.23,2573.03 5363.63,2517.84 5336.04,2573.03 ; 5336.04,2642.02 5391.23,2642.02 5391.23,2697.21 5336.04,2697.21 5336.04,2642.02 ; 5336.04,2890.37 5363.63,2904.17 5391.23,2890.37 5377.43,2917.97 5391.23,2945.56 5363.63,2931.76 5336.04,2945.56 5349.83,2917.97 5336.04,2890.37 ; 5336.04,3014.55 5391.23,3014.55 5391.23,3069.74 5336.04,3069.74 5336.04,3014.55 ; 5336.04,3152.52 5349.83,3152.52 5363.63,3138.72 5377.43,3152.52 5391.23,3152.52 5377.43,3166.32 5391.23,3180.12 5377.43,3180.12 5363.63,3193.91 5349.83,3180.12 5336.04,3180.12 5349.83,3166.32 5336.04,3152.52 ; 5336.04,3262.9 5336.04,3276.7 5349.83,3290.5 5336.04,3304.29 5336.04,3318.09 5349.83,3318.09 5363.63,3304.29 5377.43,3318.09 5391.23,3318.09 5391.23,3304.29 5377.43,3290.5 5391.23,3276.7 5391.23,3262.9 5377.43,3262.9 5363.63,3276.7 5349.83,3262.9 5336.04,3262.9 ; 5347.07,3025.59 5380.19,3025.59 5380.19,3058.7 5347.07,3058.7 5347.07,3025.59
  lines w12: 5286,2356.42 8516.52,2356.42 ; 5286,3349.82 8516.52,3349.82 ; 5623.86,2232.24 5623.86,3474 ; 5955.86,2232.24 5955.86,3474 ; 6592.42,2232.24 6592.42,3474 ; 6851.53,2232.24 6851.53,3474 ; 7226.68,2232.24 7226.68,3474 ; 7950.06,2232.24 7950.06,3474 ; 5286,2232.24 8516.52,2232.24 8516.52,3474 5286,3474 5286,2232.24
  text "Symbol" at 5360.51,3387.08 h72
  text "Quantity" at 5661.11,3387.08 h72
  text "Finished Hole Size" at 5993.12,3387.08 h72
  text "Plated" at 6629.67,3387.08 h72
  text "Hole Type" at 6888.78,3387.08 h72
  text "Drill Layer Pair" at 7263.93,3387.08 h72
  text "Hole Tolerance" at 7987.32,3387.08 h72
  text "15" at 5661.11,3262.9 h60
  text "7.87mil (0.200mm)" at 5993.12,3262.9 h60
  text "PTH" at 6629.67,3262.9 h60
  text "Round" at 6888.78,3262.9 h60
  text "Top Layer - Bottom Layer" at 7263.93,3262.9 h60
  text "2" at 5661.11,3138.72 h60
  text "8.00mil (0.203mm)" at 5993.12,3138.72 h60
  text "PTH" at 6629.67,3138.72 h60
  text "Round" at 6888.78,3138.72 h60
  text "Top Layer - Bottom Layer" at 7263.93,3138.72 h60
  text "496" at 5661.11,3014.55 h60
  text "10.00mil (0.254mm)" at 5993.12,3014.55 h60
  text "PTH" at 6629.67,3014.55 h60
  text "Round" at 6888.78,3014.55 h60
  text "Top Layer - Bottom Layer" at 7263.93,3014.55 h60
  text "15" at 5661.11,2890.37 h60
  text "40.00mil (1.016mm)" at 5993.12,2890.37 h60
  text "PTH" at 6629.67,2890.37 h60
  text "Round" at 6888.78,2890.37 h60
  text "Top Layer - Bottom Layer" at 7263.93,2890.37 h60
  text "12" at 5661.11,2766.2 h60
  text "45.28mil (1.150mm)" at 5993.12,2766.2 h60
  text "PTH" at 6629.67,2766.2 h60
  text "Round" at 6888.78,2766.2 h60
  text "Top Layer - Bottom Layer" at 7263.93,2766.2 h60
  text "1" at 5661.11,2642.02 h60
  text "52.00mil (1.321mm)" at 5993.12,2642.02 h60
  text "PTH" at 6629.67,2642.02 h60
  text "Round" at 6888.78,2642.02 h60
  text "Top Layer - Bottom Layer" at 7263.93,2642.02 h60
  text "6" at 5661.11,2517.84 h60
  text "59.06mil (1.500mm)" at 5993.12,2517.84 h60
  text "PTH" at 6629.67,2517.84 h60
  text "Round" at 6888.78,2517.84 h60
  text "Top Layer - Bottom Layer" at 7263.93,2517.84 h60
  text "4" at 5661.11,2393.67 h60
  text "125.98mil (3.200mm)" at 5993.12,2393.67 h60
  text "PTH" at 6629.67,2393.67 h60
  text "Round" at 6888.78,2393.67 h60
  text "Top Layer - Bottom Layer" at 7263.93,2393.67 h60
  text "551 Total" at 5661.11,2269.49 h60
  text ".Layer_Name" at 577,-858.49 h60
M17 Embedded Cavity:
  text ".Layer_Name" at 577,-858.49 h60
M18 Embedded Assembly:
  text ".Layer_Name" at 577,-858.49 h60
M19 Embedded Keepout:
  text ".Layer_Name" at 577,-858.49 h60

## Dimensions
0,-400 to 1000,-400 on M2 Board Dimensions
0,0 to 3937.01,0 on M2 Board Dimensions
0,0 to 0,3543.31 on M2 Board Dimensions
